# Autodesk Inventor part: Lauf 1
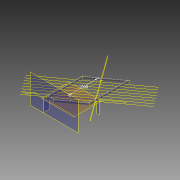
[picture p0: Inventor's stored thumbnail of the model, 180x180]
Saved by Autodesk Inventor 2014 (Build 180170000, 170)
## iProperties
Created: 2013-09
Part Number: Lauf 1
Material: Edelstahl
Document SubType Name: Modeling
Designer: Stefan Tammegger
Density: 8.08 g/cm^3
Appearance: Halbpoliert
Mass: 14509.5 g
Surface Area: 16225.1 cm^2
Volume: 1795.74 cm^3
Author: Stefan Tammegger
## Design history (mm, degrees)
node "Blöcke"
  sketch "FR 50 30 2"
    geometry: L1 (-39.377, 51.937)-(-65.377, 51.937); L2 (-67.377, 53.937)-(-67.377, 99.937); L3 (-65.377, 101.937)-(-39.377, 101.937); L4 (-37.377, 99.937)-(-37.377, 53.937); L5 (-39.377, 53.937)-(-65.377, 53.937); L6 (-65.377, 53.937)-(-65.377, 99.937); L7 (-65.377, 99.937)-(-39.377, 99.937); L8 (-39.377, 99.937)-(-39.377, 53.937); A1 r 2 centre (-39.377, 53.937) between (-39.377, 51.937) and (-37.377, 53.937); A2 r 2 centre (-39.377, 99.937) between (-37.377, 99.937) and (-39.377, 101.937); A3 r 2 centre (-65.377, 99.937) between (-65.377, 101.937) and (-67.377, 99.937); A4 r 2 centre (-65.377, 53.937) between (-67.377, 53.937) and (-65.377, 51.937); 4 further points
    constraints: 16 end point, 8 point on circle, 8 tangent, 6 point on line, 4 centre point, 4 parallel, 3 equal radius, 2 perpendicular, 1 horizontal, 1 midpoint, 3 other
    dimensions: "d1" = 30 distance of point (-67.377, 101.937) point (-37.377, 101.937); "d2" = 50 distance of point (-67.377, 51.937) point (-67.377, 101.937); "d3" = 2 distance between parallel lines of L2 L6; "d4" = 2 radius of A1
workplane "Arbeitsebene1"
sketch "Skizze1"
  geometry: L1 (-604.342, -148.845)-(-604.342, -328.845) reference; L2 (495.658, -328.845)-(-1004.342, -328.845) reference; L3 (-324.342, -148.845)-(-604.342, -148.845) reference; L4 (415.658, 541.155)-(345.658, 541.155) reference; L5 (345.658, 541.155)-(345.658, 376.155) reference; L6 (415.658, 231.155)-(415.658, 541.155) reference; L7 (345.658, 541.155)-(-604.342, -148.845); L8 (-165.493, 169.897)-(-165.493, 1209.897); 2 further points
  constraints: 4 end point, 1 coincident, 1 parallel, 1 point on line
  dimensions: "d0" = 1040 distance of L8.start L8.end
  node "Referenz1"
  node "Referenz2"
  node "Referenz3"
  node "Referenz4"
  node "Referenz5"
  node "Referenz6"
workplane "Arbeitsebene2"
  workpoint "Arbeitspunkt1"
  workaxis "Arbeitsachse1"
sketch "Skizze2"
  geometry: L1 (-841.468, 0)-(-987.107, 0) reference; 2 further points
  dimensions: "d5" = 10 dimension on L1; "d6" = 0 dimension on point (0, 0)
extrude "Extrusion1" new body sketch "Skizze2" stored distance "d7" = 4000; taper "d8" = 0 deg
workplane "Arbeitsebene3"
sketch "Skizze3"
  geometry: L1 (-400, 0)-(-400, -400) reference; L2 (-680, 0)-(-400, 0) reference; L3 (762.905, 60)-(778.185, 60) reference; 1 further point
  constraints: 1 horizontal
  dimensions: "d9" = 50 dimension on L1
extrude "Extrusion2" new body sketch "Skizze3" distance "d10" = 1500; taper "d11" = 0 deg
workpoint "Arbeitspunkt2"
sketch "Skizze4"
  geometry: L1 (-2, 60)-(-28, 60) reference; 2 further points
  constraints: 1 horizontal, 1 other
  dimensions: "d12" = 50 dimension on point (-1033.013, 0)
extrude "Extrusion3" new body sketch "Skizze4" stored distance "d13" = 3000; taper "d14" = 0 deg
workplane "Arbeitsebene4"
sketch "Skizze5"
  geometry: L1 (-70, -400)-(-70, 165) reference; L2 (-1123.511, 10)-(-1108.232, 10) reference; 1 further point
  constraints: 1 horizontal
  dimensions: "d15" = 30 dimension on L1
extrude "Extrusion4" new body sketch "Skizze5" stored distance "d16" = 3000; taper "d17" = 0 deg
workplane "Arbeitsebene5"
sketch "Skizze6"
  geometry: L1 (0, -400)-(0, 500) reference; L2 (0, 60)-(-1500, 60) reference; 2 further points
  constraints: 1 horizontal
  dimensions: "d18" = 50 dimension on L1
extrude "Extrusion5" new body sketch "Skizze6" distance "d19" = 500; taper "d20" = 0 deg
workplane "Arbeitsebene6"
feature "Trennen1"
feature "Trennen2"
workplane "Arbeitsebene7"
feature "Trennen3"
feature "Trennen4"
workplane "Arbeitsebene8"
feature "Trennen5"
feature "Trennen6"
workplane "Arbeitsebene9"
feature "Trennen7"
feature "Trennen8"
workplane "Arbeitsebene10"
feature "Trennen9"
feature "Trennen10"
sketch "Skizze7"
  geometry: L1 (52, 128)-(-228, 128) reference; L2 (52, -52)-(52, 128) reference; L3 (452, -52)-(-1048, -52) reference; L4 (-28, 28)-(-221.343, 28) reference; L5 (2, -2)-(-231.088, -2) reference; L6 (-28, 28)-(-28, 1189.027) reference; L7 (2, -2)-(2, 1204.316) reference; L8 (-63, 98)-(37, 98); L9 (37, 98)-(37, -2); L10 (37, -2)-(-63, -2); L11 (-63, -2)-(-63, 98); L12 (-13, 173.694)-(-13, 150.348); 1 further point
  constraints: 10 end point, 3 parallel, 1 collinear, 1 horizontal, 1 perpendicular, 1 other
  dimensions: "d22" = 100 distance of L8.end L9.end; "d23" = 15 distance between parallel lines of L7 L12; "d44" = 50 distance between parallel lines of L9 L12
  node "Referenz12"
  node "Referenz13"
  node "Referenz14"
workplane "Arbeitsebene11"
extrude "Extrusion6" new body sketch "Skizze7" stored distance "d24" = 3000; taper "d25" = 0 deg
hole "Bohrung1" diameter "d28" = 12; stored, may be unused: countersink angle "d32" = 90 deg, drill point angle "d34" = 118 deg; dims "d26" = 20, "d27" = 50, "d29" = 6, "d30" = 4, "d31" = 2, "d33" = 8
hole "Bohrung2" diameter "d37" = 12; stored, may be unused: countersink angle "d41" = 90 deg, drill point angle "d43" = 118 deg; dims "d35" = 15, "d36" = 50, "d38" = 6, "d39" = 4, "d40" = 2, "d42" = 8
sketch "Skizze8"
  geometry: L1 (28, 1315.725)-(28, 14.269) reference; L2 (-2, 1374.592)-(-2, -1.019) reference; L3 (-2, -1.019)-(704.912, -514.46) reference; L4 (80, 120)-(0, 120); L5 (0, 120)-(0, 0); L6 (0, 0)-(80, 0); L7 (80, 0)-(80, 120); L8 (0, 1370.668)-(0, 0) reference; 1 further point
  constraints: 8 end point, 2 parallel, 1 collinear, 1 horizontal, 1 perpendicular
  dimensions: "d68" = 80 distance of L4.start L4.end; "d69" = 120 distance of L6.end L4.start; "d70" = 0 distance from line of L6 L8.end
workplane "Arbeitsebene12"
extrude "Extrusion7" new body sketch "Skizze8" stored distance "d48" = 3000; taper "d49" = 0 deg
hole "Bohrung5" diameter "d73" = 12; stored, may be unused: countersink angle "d77" = 90 deg, drill point angle "d79" = 118 deg; dims "d71" = 20, "d72" = 20, "d74" = 6, "d75" = 4, "d76" = 2, "d78" = 8
hole "Bohrung6" diameter "d82" = 12; stored, may be unused: countersink angle "d86" = 90 deg, drill point angle "d88" = 118 deg; dims "d80" = 20, "d81" = 20, "d83" = 6, "d84" = 4, "d85" = 2, "d87" = 8
sketch "Skizze9" dims "d97" = 10
  geometry: L1 (-30, 58)-(-30, 12) reference; L2 (-975.592, 60)-(-2, 60) reference; L3 (-975.592, 10)-(-2, 10) reference; L4 (-1085.013, 60)-(-1111.013, 60) reference; L5 (-1083.013, 58)-(-1083.013, 12) reference; L6 (-30, 35)-(-1083.013, 35); C1 r 2.5 at (-147.001, 35); C2 r 2.5 at (-264.002, 35); C3 r 2.5 at (-381.003, 35); C4 r 2.5 at (-498.004, 35); C5 r 2.5 at (-615.005, 35); C6 r 2.5 at (-732.006, 35); C7 r 2.5 at (-849.007, 35); C8 r 2.5 at (-966.008, 35); 1 further point
  constraints: 8 centre point, 2 end point, 2 midpoint, 1 horizontal, 1 point on line, 14 other
  dimensions: "d89" = 5 diameter of C1; "d90" = 1053.01317 distance of L6.end L6.start (derived); "d91" = 117.00146 distance from line of C1.centre L1 (= 0.111111 x d90); "d94" = 117.001 distance of C1.centre C2.centre
extrude "Extrusion8" new body sketch "Skizze9" stored distance "d99" = 3000; taper "d100" = 0 deg
sketch "Skizze11"
  geometry: 17 further points; 8 other entities
  constraints: 8 coincident, 8 other
hole "Bohrung8" sketch "Skizze11" diameter "d110" = 6; stored, may be unused: countersink angle "d114" = 90 deg, drill point angle "d116" = 118 deg; dims "d111" = 6, "d112" = 4, "d113" = 2, "d115" = 8
sketch "Skizze12"
  geometry: 9 further points; 8 other entities
  constraints: 8 other
hole "Bohrung9" sketch "Skizze12" at (23, -181.684), (23, -326.29), (23, -470.895), (23, -615.501), (23, -760.107), (23, -904.712), (23, -1049.318), (23, -1193.923) diameter "d117" = 6; stored, may be unused: countersink angle "d121" = 90 deg, drill point angle "d123" = 118 deg; dims "d118" = 6, "d119" = 4, "d120" = 2, "d122" = 8
workplane "Arbeitsebene13"
sketch "Skizze13"
  geometry: C1 r 5 at (-147.001, 35.588); 2 further points; 1 other entity
  constraints: 1 centre point, 1 other
  dimensions: "d125" = 10 diameter of C1
extrude "Extrusion9" new body sketch "Skizze13" stored distance "d126" = 3000; taper "d127" = 0 deg
workplane "Arbeitsebene14"
sketch "Skizze14"
  geometry: C1 r 5 at (-147.001, 35); 2 further points; 1 other entity
  constraints: 1 centre point, 1 coincident, 1 other
  dimensions: "d132" = 10 diameter of C1
extrude "Extrusion10" new body sketch "Skizze14" stored distance "d133" = 3000; taper "d134" = 0 deg
sketch "Skizze15"
  geometry: C1 r 5 at (0, 0) reference; 1 further point
hole "Bohrung10" sketch "Skizze15" at (0, 0) diameter "d138" = 6; stored, may be unused: countersink angle "d142" = 90 deg, drill point angle "d144" = 118 deg; dims "d139" = 6, "d140" = 4, "d141" = 2, "d143" = 8
sketch "Skizze16"
  geometry: C1 r 5 at (0, 0) reference; 1 further point
hole "Bohrung11" sketch "Skizze16" at (0, 0) diameter "d145" = 6; stored, may be unused: countersink angle "d149" = 90 deg, drill point angle "d151" = 118 deg; dims "d146" = 6, "d147" = 4, "d148" = 2, "d150" = 8
pattern_linear "Rechteckige Anordnung3" dims "d154" = 144.606
node "Volumenkörper1"
node "Referenz7"
node "Referenz8"
node "Referenz9"
node "Referenz10"
node "Referenz11"
node "Volumenkörper2"
node "Volumenkörper3"
node "Volumenkörper4"
node "Volumenkörper5"
node "Volumenkörper6"
node "Volumenkörper7"
node "Volumenkörper8"
node "Volumenkörper9"
node "Volumenkörper10"
node "FR 50 30 2:1" dims "d5" = 10, "d6" = 0
node "FR 50 30 2:2" dims "d9" = 50
node "FR 50 30 2:3" dims "d12" = 50
node "FR 50 30 2:4" dims "d15" = 30
node "FR 50 30 2:5" dims "d18" = 50
other parameters: "d124" = -592, "d131" = 578.75
